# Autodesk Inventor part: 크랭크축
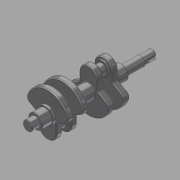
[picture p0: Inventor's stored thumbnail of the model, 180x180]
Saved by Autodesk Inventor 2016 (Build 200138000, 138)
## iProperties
Created: 2017-03
Part Number: 크랭크축
Material: 강철, 탄소
Document SubType Name: Modeling
Designer: mduedu
Density: 7.87 g/cm^3
Mass: 2638.48 g
Surface Area: 631.346 cm^2
Volume: 335.258 cm^3
Appearance: 반광택
Author: mduedu
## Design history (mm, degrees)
sketch "스케치1" dims "d5" = 65
  geometry: L1 (-19, 26.368)-(-19, 8.368); L2 (-19, 8.368)-(-44.545, -6.381); L3 (19, 26.368)-(19, 8.368); L4 (0, 26.368)-(0, -45); L5 (19, 8.368)-(44.545, -6.381); C1 r 10 at (0, 0); C2 r 17.5 at (0, 0); A1 r 45 centre (0, 0) between (-44.545, -6.381) and (0, -45); A2 r 45 centre (0, 0) between (0, -45) and (44.545, -6.381); A3 r 19 centre (0, 26.368) between (19, 26.368) and (0, 45.368); A4 r 19 centre (0, 26.368) between (0, 45.368) and (-19, 26.368); 3 further points
  constraints: 10 end point, 8 point on circle, 6 centre point, 5 coincident, 3 symmetric about line, 2 point on line, 1 parallel, 1 tangent, 1 vertical, 1 vertical alignment, 5 other
  dimensions: "d0" = 20 diameter of C1; "d1" = 35 diameter of C2; "d2" = 18 distance of L1.start L1.end; "d3" = 120 deg angle of L2 L1; "d4" = 45 radius of A1; "d6" = 19 radius of A4
extrude "돌출1" new body sketch "스케치1" distance "d7" = 12; taper "d8" = 0 deg
extrude "돌출2" join sketch "스케치1" distance "d9" = 5; taper "d10" = 0 deg
extrude "돌출3" join sketch "스케치1" distance "d11" = 90; taper "d12" = 0 deg
sketch "스케치2"
  geometry: C1 r 15 at (0, 26.368); C2 r 10 at (0, 26.368); A1 r 19 centre (0, 26.368) between (19, 26.368) and (-19, 26.368) reference; 1 further point
  constraints: 2 centre point, 2 coincident
  dimensions: "d13" = 30 diameter of C1; "d14" = 20 diameter of C2
extrude "돌출4" join sketch "스케치2" distance "d15" = 3; taper "d16" = 0 deg
extrude "돌출5" join sketch "스케치2" distance "d17" = 16; taper "d18" = 0 deg
fillet "모깎기1" dims "d19" = 3, "d20" = 10
fillet "모깎기2" dims "d21" = 2
sketch "스케치3"
  geometry: C1 r 15 at (0, 0); 1 further point
  constraints: 1 centre point, 1 coincident
  dimensions: "d22" = 30 diameter of C1
extrude "돌출6" join sketch "스케치3" distance "d23" = 21; taper "d24" = 0 deg
sketch "스케치4"
  geometry: C1 r 10 at (0, 0) reference; C2 r 9 at (0, 0); 1 further point
  constraints: 1 centre point
  dimensions: "d25" = 1 radial gap between concentric circles of C1 C2
extrude "돌출7" cut sketch "스케치4" distance "d26" = 25; taper "d27" = 0 deg
node "작업 평면1"
sketch "스케치5"
  geometry: L1 (-9, 0)-(9, 0) reference; L2 (-3, 0)-(3, 0); L3 (3, 0)-(3, 15); L4 (-3, 15)-(-3, 0); A1 r 3 centre (0, 15) between (3, 15) and (-3, 15); 1 further point
  constraints: 6 end point, 2 point on circle, 2 tangent, 1 centre point, 1 horizontal, 1 parallel, 1 perpendicular, 1 point on line, 1 vertical alignment
  dimensions: "d28" = 6 distance between parallel lines of L3 L4; "d30" = 18 dimension on A1 L1
extrude "돌출8" cut sketch "스케치5" distance "d31" = 3.5; taper "d32" = 0 deg
chamfer "모따기1" distance "d33" = 1; stored, may be unused: second distance "d34" = 2, angle "d35" = 45 deg
chamfer "모따기2" distance "d36" = 1; stored, may be unused: second distance "d37" = 2, angle "d38" = 45 deg
node "작업 평면2"
sketch "스케치6"
  geometry: C1 r 15 at (0, 0) reference; C2 r 15 at (0, 0) reference; 1 further point
extrude "돌출9" join sketch "스케치6" distance "d39" = 42; taper "d40" = 0 deg
sketch "스케치7" dims "d46" = 65
  geometry: L1 (-19, -26.368)-(-19, -8.368); L2 (19, -26.368)-(19, -8.368); L3 (-19, -8.368)-(-44.545, 6.381); L4 (19, -8.368)-(44.545, 6.381); L5 (0, -26.368)-(0, 45); C1 r 17.5 at (0, 0); C2 r 10 at (0, 0); A1 r 19 centre (0, -26.368) between (0, -45.368) and (19, -26.368); A2 r 19 centre (0, -26.368) between (-19, -26.368) and (0, -45.368); A3 r 45 centre (0, 0) between (0, 45) and (-44.545, 6.381); A4 r 45 centre (0, 0) between (44.545, 6.381) and (0, 45); 3 further points
  constraints: 10 end point, 8 point on circle, 6 centre point, 5 coincident, 3 symmetric about line, 2 point on line, 1 parallel, 1 tangent, 1 vertical, 5 other
  dimensions: "d41" = 20 diameter of C2; "d42" = 35 diameter of C1; "d43" = 18 distance of L2.start L2.end; "d44" = 120 deg angle of L4 L2; "d45" = 45 radius of A4; "d47" = 19 radius of A1
extrude "돌출10" join sketch "스케치7" distance "d48" = 12; taper "d49" = 0 deg
sketch "스케치8"
  geometry: C1 r 15 at (0, -26.368); C2 r 10 at (0, -26.368); A1 r 19 centre (0, -26.368) between (-19, -26.368) and (19, -26.368) reference; 1 further point
  constraints: 2 centre point, 2 coincident
  dimensions: "d50" = 30 diameter of C1; "d51" = 20 diameter of C2
extrude "돌출11" join sketch "스케치8" distance "d52" = 3; taper "d53" = 0 deg
extrude "돌출12" join sketch "스케치8" distance "d54" = 16; taper "d55" = 0 deg
fillet "모깎기3" dims "d56" = 3, "d57" = 10
fillet "모깎기4" dims "d58" = 2
chamfer "모따기3" distance "d59" = 1; stored, may be unused: second distance "d60" = 2, angle "d61" = 45 deg
node "작업 평면3"
fillet "모깎기5" dims "d62" = 1
sketch "스케치9"
  geometry: C1 r 17.5 at (0, 0) reference; 1 further point
extrude "돌출13" join sketch "스케치9" distance "d63" = 5; taper "d64" = 0 deg
sketch "스케치10"
  geometry: C1 r 10 at (0, 0) reference; 1 further point
extrude "돌출14" join sketch "스케치10" distance "d65" = 36; taper "d66" = 0 deg
sketch "스케치11"
  geometry: C1 r 15 at (0, 0); 1 further point
  constraints: 1 centre point, 1 coincident
  dimensions: "d67" = 30 diameter of C1
extrude "돌출15" join sketch "스케치11" distance "d68" = 20; taper "d69" = 0 deg
chamfer "모따기4" distance "d70" = 1; stored, may be unused: second distance "d71" = 2, angle "d72" = 45 deg
node "솔리드1"
mirror "대칭1"
mirror "대칭2"
node "투영된 루프1"
